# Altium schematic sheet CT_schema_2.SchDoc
size 271 x 273 mm
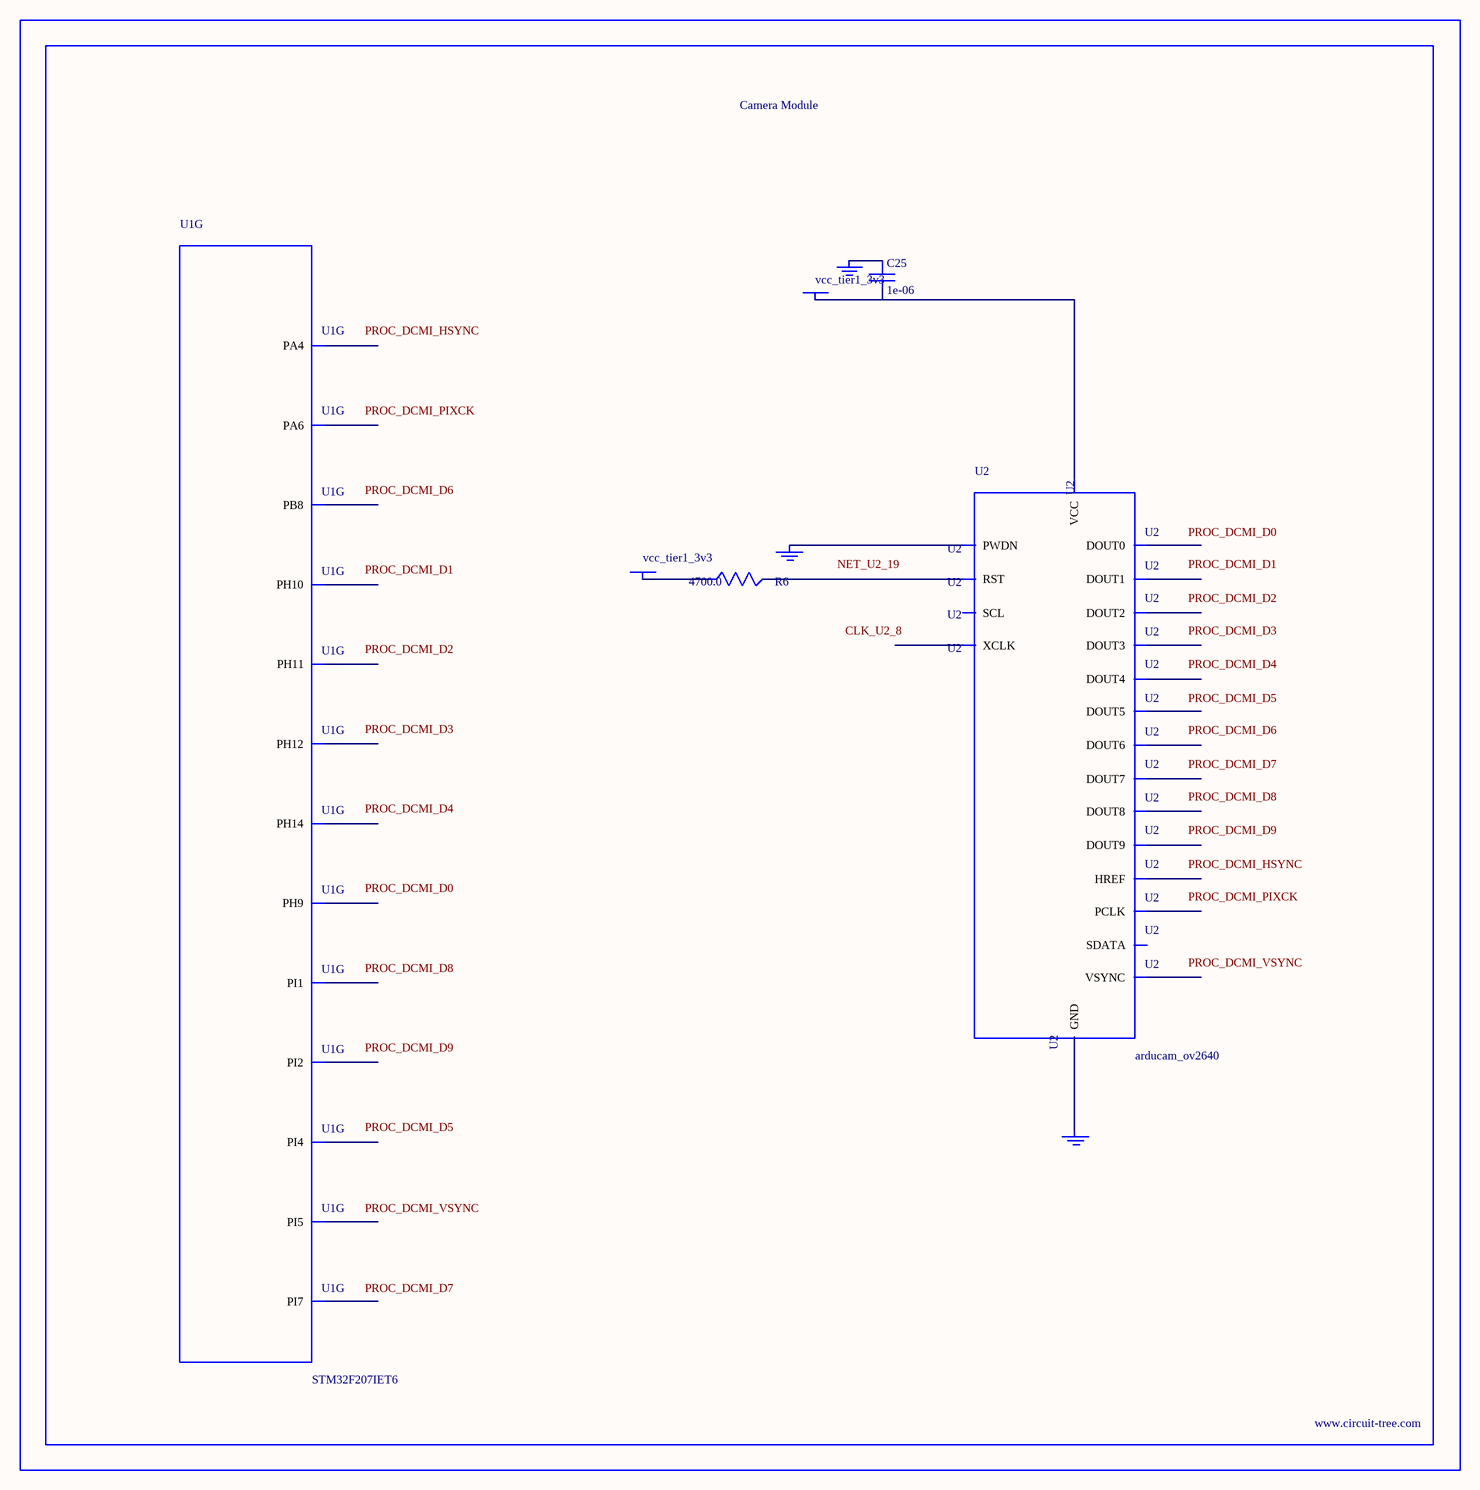
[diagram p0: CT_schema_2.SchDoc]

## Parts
BORDER1  (no value)
C25  1e-06  [C0603]
GND_INSTANCE_1_0  (no value)
GND_INSTANCE_1_1  (no value)
GND_INSTANCE_1_2  (no value)
POWER_INSTANCE_1_0  vcc_tier1_3v3
POWER_INSTANCE_1_1  vcc_tier1_3v3
R6  4700.0  [R0603]
U1  STM32F207IET6  [LQFP176]  (part G of 11)
U2  arducam_ov2640  [ARDUCAM]

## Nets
NetC25_1: C25.1 GND_INSTANCE_1_0.0(GND)
NetC25_2: C25.2 POWER_INSTANCE_1_0.0(PWR) U2.1(VCC)
NetGND_INSTANCE_1_1_0: GND_INSTANCE_1_1.0(GND) U2.20(PWDN)
NetGND_INSTANCE_1_2_0: GND_INSTANCE_1_2.0(GND) U2.2(GND)
NetPOWER_INSTANCE_1_1_0: POWER_INSTANCE_1_1.0(PWR) R6.1
NetR6_2: R6.2 U2.19(RST)

Not connected (* = marked no-connect by the designer): U1 50(PA4) 52(PA6) 86(PH9) 87(PH10) 88(PH11) 89(PH12) 129(PH14) 132(PI1) 133(PI2) 167(PB8) 173(PI4) 174(PI5) 176(PI7); U2 3(SCL) 4(SDATA) 5(VSYNC) 6(HREF) 7(PCLK) 8(XCLK) 9(DOUT9) 10(DOUT8) 11(DOUT7) 12(DOUT6) 13(DOUT5) 14(DOUT4) 15(DOUT3) 16(DOUT2) 17(DOUT1) 18(DOUT0)

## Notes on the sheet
- Labels drawn without touching a wire or pin: CLK_U2_8, NET_U2_19, PROC_DCMI_D0, PROC_DCMI_D1, PROC_DCMI_D2, PROC_DCMI_D3, PROC_DCMI_D4, PROC_DCMI_D5, PROC_DCMI_D6, PROC_DCMI_D7, PROC_DCMI_D8, PROC_DCMI_D9, PROC_DCMI_HSYNC, PROC_DCMI_PIXCK, PROC_DCMI_VSYNC

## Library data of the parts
BORDER1 = BORDER_PAGE1
C25 = C0603C105K3RACTU
GND_INSTANCE_1_0-GND_INSTANCE_1_2 = GND
POWER_INSTANCE_1_0 POWER_INSTANCE_1_1 = PWR
R6 = RC0603JR-074K7L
